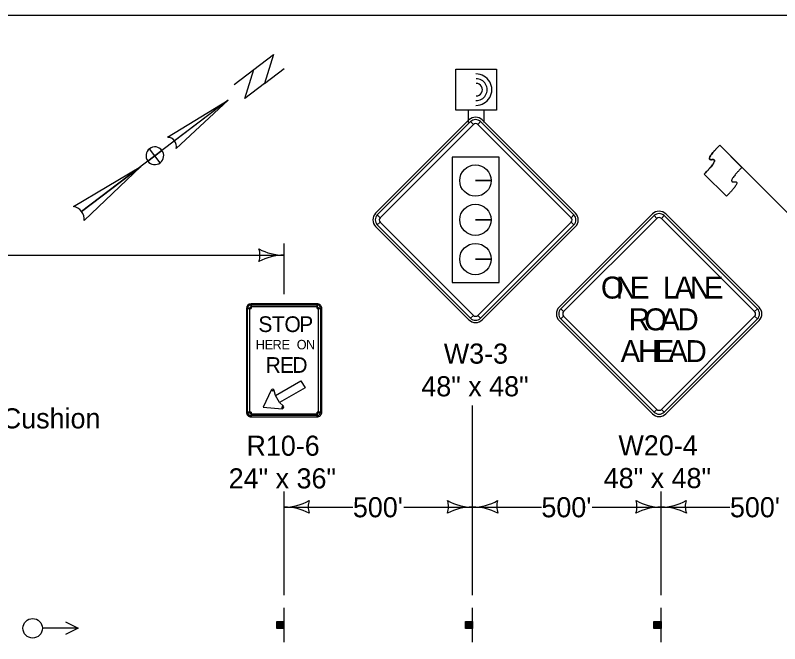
# Model space of a CAD drawing. Extents: x -2134934 to -2119606, y -2139046 to -2137036.
# Drawn here: x -2132728 to -2132120, y -2137536 to -2137036 of the extents above; entities that cross this region are included whole.
import ezdxf

# ---------------------------------------------------------------- set-up
doc = ezdxf.new("R2010")
doc.units = 0
for name, color, linetype in [('Default', 7, 'Continuous'), ('dsnCellElements', 7, 'Continuous'), ('dsnCellsScaleBlock', 7, 'Continuous'), ('dsnStdLabel', 7, 'Continuous'), ('Level 2', 7, 'Continuous'), ('Level 5', 7, 'Continuous')]:
    doc.layers.add(name, color=color, linetype=linetype)

msp = doc.modelspace()

# ---------------------------------------------------------------- linework, layer by layer
at = {"layer": 'Default'}
msp.add_lwpolyline([(-2134934.44, -2137035.95), (-2131799.45, -2137035.95), (-2131799.45, -2139045.94), (-2134934.44, -2139045.94)], close=True, dxfattribs=at)
at = {"layer": 'dsnCellElements'}
for centre, radius, start, end in [((-2132550.08, -2137226.98), 16.42, 342.26665, 17.73335), ((-2132514.45, -2137184.48), 42.5, 241.92751, 270), ((-2132514.45, -2137269.48), 42.5, 90, 118.07249)]:
    msp.add_arc(centre, radius, start, end, dxfattribs=at)
at = {"layer": 'dsnCellsScaleBlock'}
for p, q in [((-2132558.93, -2137103.5), (-2132675.59, -2137192.09)), ((-2132558.93, -2137103.5), (-2132600.39, -2137142.06)), ((-2132607.2, -2137133.09), (-2132607.2, -2137133.09)), ((-2132606.66, -2137132.95), (-2132605.09, -2137133.07)), ((-2132622.86, -2137152.05), (-2132622.87, -2137152.06)), ((-2132682.09, -2137188.19), (-2132628.47, -2137156.31))]:
    msp.add_line(p, q, dxfattribs=at)
for points in [[(-2132554.21, -2137091.08), (-2132522.8, -2137067.23), (-2132529.99, -2137090.37), (-2132514.28, -2137078.45)], [(-2132607.2, -2137133.09), (-2132558.93, -2137103.5), (-2132601.55, -2137135.87)], [(-2132622.87, -2137152.06), (-2132617.26, -2137147.8), (-2132621.52, -2137142.19)], [(-2132613, -2137153.41), (-2132617.26, -2137147.8), (-2132611.65, -2137143.54)], [(-2132675.59, -2137192.09), (-2132628.47, -2137156.31), (-2132673.57, -2137199.41)]]:
    msp.add_lwpolyline(points, dxfattribs=at)
msp.add_lwpolyline([(-2132545.69, -2137102.3), (-2132538.5, -2137079.15), (-2132522.8, -2137067.23), (-2132529.99, -2137090.37)], close=True, dxfattribs=at)
for centre, radius, start, end in [((-2132607.16, -2137140.13), 7.04, 37.23253, 90.33788), ((-2132607.15, -2137140.13), 7.04, 344.06021, 37.23398), ((-2132617.26, -2137147.8), 7.04, 127.21215, 217.21215), ((-2132617.26, -2137147.8), 7.04, 37.21215, 127.21215), ((-2132617.26, -2137147.8), 7.04, 307.21215, 37.21215), ((-2132617.26, -2137147.8), 7.04, 217.21215, 307.21215), ((-2132683.72, -2137198.26), 10.2, 37.20154, 80.8311), ((-2132683.72, -2137198.27), 10.21, 353.61421, 37.21279)]:
    msp.add_arc(centre, radius, start, end, dxfattribs=at)
at = {"layer": 'dsnStdLabel'}
for p, q in [((-2132367.37, -2137119.33), (-2132441.62, -2137193.57)), ((-2132366.05, -2137120.65), (-2132363.84, -2137122.86)), ((-2132360.3, -2137122.86), (-2132358.09, -2137120.65)), ((-2132282.52, -2137193.57), (-2132356.77, -2137119.33)), ((-2132110.46, -2137196.68), (-2132167.8, -2137139.38)), ((-2132167.8, -2137139.38), (-2132150.11, -2137157.06)), ((-2132162.49, -2137180.05), (-2132180.17, -2137162.37)), ((-2132349.66, -2137167.55), (-2132362.16, -2137167.55)), ((-2132362.16, -2137167.55), (-2132349.66, -2137167.55)), ((-2132438.08, -2137197.11), (-2132440.29, -2137194.9)), ((-2132221.34, -2137194.14), (-2132295.58, -2137268.39)), ((-2132283.85, -2137194.9), (-2132286.06, -2137197.11)), ((-2132136.48, -2137268.39), (-2132210.73, -2137194.14)), ((-2132440.29, -2137202.85), (-2132438.08, -2137200.64)), ((-2132349.66, -2137198.8), (-2132362.16, -2137198.8)), ((-2132362.16, -2137198.8), (-2132349.66, -2137198.8)), ((-2132286.06, -2137200.64), (-2132283.85, -2137202.85)), ((-2132220.01, -2137195.47), (-2132217.8, -2137197.68)), ((-2132214.27, -2137197.68), (-2132212.06, -2137195.47)), ((-2132441.62, -2137204.18), (-2132367.37, -2137278.43)), ((-2132356.77, -2137278.43), (-2132282.52, -2137204.18)), ((-2132349.66, -2137230.05), (-2132362.16, -2137230.05)), ((-2132362.16, -2137230.05), (-2132349.66, -2137230.05)), ((-2132540.7, -2137269.41), (-2132540.7, -2137265.66)), ((-2132540.7, -2137268.16), (-2132540.7, -2137266.6)), ((-2132488.2, -2137265.66), (-2132488.2, -2137269.41)), ((-2132488.2, -2137266.6), (-2132488.2, -2137268.16)), ((-2132544.45, -2137269.41), (-2132540.7, -2137269.41)), ((-2132543.51, -2137269.41), (-2132541.95, -2137269.41)), ((-2132488.2, -2137269.41), (-2132484.45, -2137269.41)), ((-2132486.95, -2137269.41), (-2132485.38, -2137269.41)), ((-2132292.05, -2137271.93), (-2132294.26, -2137269.72)), ((-2132137.81, -2137269.72), (-2132140.02, -2137271.93)), ((-2132363.84, -2137274.89), (-2132366.05, -2137277.1)), ((-2132358.09, -2137277.1), (-2132360.3, -2137274.89)), ((-2132295.58, -2137279), (-2132221.34, -2137353.24)), ((-2132294.26, -2137277.67), (-2132292.05, -2137275.46)), ((-2132210.73, -2137353.24), (-2132136.48, -2137279)), ((-2132140.02, -2137275.46), (-2132137.81, -2137277.67)), ((-2132524.59, -2137334.4), (-2132523.48, -2137334.98)), ((-2132523.48, -2137334.98), (-2132522.26, -2137334.7)), ((-2132540.7, -2137351.91), (-2132544.45, -2137351.91)), ((-2132541.95, -2137351.91), (-2132543.51, -2137351.91)), ((-2132540.7, -2137355.66), (-2132540.7, -2137351.91)), ((-2132515.98, -2137347.97), (-2132516.03, -2137349.22)), ((-2132515.13, -2137347.05), (-2132515.98, -2137347.97)), ((-2132484.45, -2137351.91), (-2132488.2, -2137351.91)), ((-2132488.2, -2137351.91), (-2132488.2, -2137355.66)), ((-2132485.38, -2137351.91), (-2132486.95, -2137351.91)), ((-2132217.8, -2137349.71), (-2132220.01, -2137351.92)), ((-2132212.06, -2137351.92), (-2132214.27, -2137349.71)), ((-2132540.7, -2137354.72), (-2132540.7, -2137353.16)), ((-2132488.2, -2137353.16), (-2132488.2, -2137354.72))]:
    msp.add_line(p, q, dxfattribs=at)
for points in [[(-2132366.05, -2137120.65), (-2132440.29, -2137194.9), (-2132438.08, -2137197.11), (-2132363.84, -2137122.86), (-2132366.05, -2137120.65)], [(-2132283.85, -2137194.9), (-2132358.09, -2137120.65), (-2132360.3, -2137122.86), (-2132286.06, -2137197.11), (-2132283.85, -2137194.9)], [(-2132343.34, -2137148.93), (-2132380.8, -2137148.93), (-2132380.8, -2137248.82), (-2132343.34, -2137248.82), (-2132343.34, -2137148.93)], [(-2132440.29, -2137202.85), (-2132366.05, -2137277.1), (-2132363.84, -2137274.89), (-2132438.08, -2137200.64), (-2132440.29, -2137202.85)], [(-2132358.09, -2137277.1), (-2132283.85, -2137202.85), (-2132286.06, -2137200.64), (-2132360.3, -2137274.89), (-2132358.09, -2137277.1)], [(-2132220.01, -2137195.47), (-2132294.26, -2137269.72), (-2132292.05, -2137271.93), (-2132217.8, -2137197.68), (-2132220.01, -2137195.47)], [(-2132137.81, -2137269.72), (-2132212.06, -2137195.47), (-2132214.27, -2137197.68), (-2132140.02, -2137271.93), (-2132137.81, -2137269.72)], [(-2132540.7, -2137355.66), (-2132488.2, -2137355.66), (-2132488.2, -2137351.91), (-2132484.45, -2137351.91), (-2132484.45, -2137269.41), (-2132488.2, -2137269.41), (-2132488.2, -2137265.66), (-2132540.7, -2137265.66), (-2132540.7, -2137269.41), (-2132544.45, -2137269.41), (-2132544.45, -2137351.91), (-2132540.7, -2137351.91), (-2132540.7, -2137355.66)], [(-2132488.2, -2137268.16), (-2132540.7, -2137268.16), (-2132540.7, -2137266.6), (-2132488.2, -2137266.6), (-2132488.2, -2137268.16)], [(-2132541.95, -2137269.41), (-2132541.95, -2137351.91), (-2132543.51, -2137351.91), (-2132543.51, -2137269.41), (-2132541.95, -2137269.41)], [(-2132486.95, -2137351.91), (-2132486.95, -2137269.41), (-2132485.38, -2137269.41), (-2132485.38, -2137351.91), (-2132486.95, -2137351.91)], [(-2132294.26, -2137277.67), (-2132220.01, -2137351.92), (-2132217.8, -2137349.71), (-2132292.05, -2137275.46), (-2132294.26, -2137277.67)], [(-2132212.06, -2137351.92), (-2132137.81, -2137277.67), (-2132140.02, -2137275.46), (-2132214.27, -2137349.71), (-2132212.06, -2137351.92)], [(-2132501.07, -2137326.91), (-2132497.79, -2137332.6), (-2132518.1, -2137344.32), (-2132521.38, -2137338.64), (-2132501.07, -2137326.91)], [(-2132531.1, -2137348.04), (-2132516.03, -2137349.22), (-2132515.98, -2137347.97), (-2132515.13, -2137347.05), (-2132518.1, -2137344.32), (-2132521.38, -2137338.64), (-2132522.26, -2137334.7), (-2132523.48, -2137334.98), (-2132524.59, -2137334.4), (-2132531.1, -2137348.04)], [(-2132540.7, -2137353.16), (-2132488.2, -2137353.16), (-2132488.2, -2137354.72), (-2132540.7, -2137354.72), (-2132540.7, -2137353.16)]]:
    msp.add_lwpolyline(points, close=True, dxfattribs=at)
for centre in [(-2132362.16, -2137167.55), (-2132362.16, -2137198.8), (-2132362.16, -2137230.05)]:
    msp.add_circle(centre, 12.5, dxfattribs=at)
for centre, radius, start, end in [((-2132362.07, -2137124.63), 7.5, 44.99999, 134.99974), ((-2132362.07, -2137124.63), 5.62, 44.99999, 134.99974), ((-2132362.07, -2137124.63), 2.5, 44.99999, 134.99974), ((-2132436.32, -2137198.88), 7.5, 134.99974, 224.99995), ((-2132436.32, -2137198.88), 5.62, 134.99974, 224.99995), ((-2132287.83, -2137198.88), 5.62, 315.00016, 44.9998), ((-2132287.83, -2137198.88), 7.5, 315.00016, 44.9998), ((-2132216.03, -2137199.45), 7.5, 44.99999, 134.99974), ((-2132216.03, -2137199.45), 5.62, 44.99999, 134.99974), ((-2132436.32, -2137198.88), 2.5, 134.99974, 224.99995), ((-2132287.83, -2137198.88), 2.5, 315.00016, 44.9998), ((-2132216.03, -2137199.45), 2.5, 44.99999, 134.99974), ((-2132540.7, -2137269.41), 3.75, 90.00021, 179.99985), ((-2132540.7, -2137269.41), 2.81, 90.00021, 179.99985), ((-2132488.2, -2137269.41), 3.75, 0, 90.00021), ((-2132488.2, -2137269.41), 2.81, 0, 90.00021), ((-2132540.7, -2137269.41), 1.25, 90.00021, 179.99985), ((-2132488.2, -2137269.41), 1.25, 0, 90.00021), ((-2132290.28, -2137273.69), 7.5, 134.99974, 224.99995), ((-2132290.28, -2137273.69), 5.62, 134.99974, 224.99995), ((-2132290.28, -2137273.69), 2.5, 134.99974, 224.99995), ((-2132141.79, -2137273.69), 2.5, 315.00016, 44.9998), ((-2132141.79, -2137273.69), 5.62, 315.00016, 44.9998), ((-2132141.79, -2137273.69), 7.5, 315.00016, 44.9998), ((-2132362.07, -2137273.12), 7.5, 224.99995, 315.00016), ((-2132362.07, -2137273.12), 5.62, 224.99995, 315.00016), ((-2132362.07, -2137273.12), 2.5, 224.99995, 315.00016), ((-2132523.48, -2137334.98), 1.25, 12.62232, 152.27557), ((-2132540.7, -2137351.91), 3.75, 179.99985, 270.00006), ((-2132540.7, -2137351.91), 2.81, 179.99985, 270.00006), ((-2132540.7, -2137351.91), 1.25, 179.99985, 270.00006), ((-2132515.98, -2137347.97), 1.25, 267.72427, 47.37758), ((-2132488.2, -2137351.91), 3.75, 270.00006, 0.00027), ((-2132488.2, -2137351.91), 2.81, 270.00006, 0.00027), ((-2132488.2, -2137351.91), 1.25, 270.00006, 0.00027), ((-2132216.03, -2137347.94), 5.62, 224.99995, 315.00016), ((-2132216.03, -2137347.94), 2.5, 224.99995, 315.00016), ((-2132216.03, -2137347.94), 7.5, 224.99995, 315.00016)]:
    msp.add_arc(centre, radius, start, end, dxfattribs=at)
for points in [[(-2132180.17, -2137162.37), (-2132167.8, -2137149.99), (-2132180.17, -2137151.77), (-2132167.8, -2137139.38)], [(-2132150.11, -2137157.06), (-2132162.49, -2137169.44), (-2132150.12, -2137167.67), (-2132162.49, -2137180.05)]]:
    msp.add_open_spline(points, degree=2, dxfattribs=at)
at = {"layer": 'Level 2'}
for p, q in [((-2132367.91, -2137111.41), (-2132367.91, -2137121.41)), ((-2132355.41, -2137111.41), (-2132355.41, -2137121.41)), ((-2132514.45, -2137258.09), (-2132514.45, -2137217.69)), ((-2133178.02, -2137226.98), (-2132514.45, -2137226.98)), ((-2132364.45, -2137497.66), (-2132364.45, -2137346.75)), ((-2132514.45, -2137497.66), (-2132514.45, -2137415.16)), ((-2132214.45, -2137497.66), (-2132214.45, -2137415.16)), ((-2132514.45, -2137427.66), (-2132459.7, -2137427.66)), ((-2132419.2, -2137427.66), (-2132364.45, -2137427.66)), ((-2132364.45, -2137427.66), (-2132309.7, -2137427.66)), ((-2132269.2, -2137427.66), (-2132214.45, -2137427.66)), ((-2132214.45, -2137427.66), (-2132159.7, -2137427.66)), ((-2132514.45, -2137535.16), (-2132514.45, -2137507.66)), ((-2132364.45, -2137535.16), (-2132364.45, -2137507.66)), ((-2132214.45, -2137535.16), (-2132214.45, -2137507.66)), ((-2132519.77, -2137524.3), (-2132519.77, -2137518.71)), ((-2132519.45, -2137518.71), (-2132519.45, -2137524.3)), ((-2132519.23, -2137524.3), (-2132519.23, -2137518.71)), ((-2132518.91, -2137518.71), (-2132518.91, -2137524.3)), ((-2132518.68, -2137524.3), (-2132518.7, -2137518.71)), ((-2132518.27, -2137518.71), (-2132518.25, -2137524.3)), ((-2132518.05, -2137524.3), (-2132518.05, -2137518.71)), ((-2132517.62, -2137518.71), (-2132517.62, -2137524.3)), ((-2132517.24, -2137524.3), (-2132517.24, -2137518.71)), ((-2132516.92, -2137518.71), (-2132516.9, -2137524.3)), ((-2132516.7, -2137524.3), (-2132516.7, -2137518.71)), ((-2132516.43, -2137518.71), (-2132516.43, -2137524.3)), ((-2132516.1, -2137524.3), (-2132516.1, -2137518.71)), ((-2132515.89, -2137518.71), (-2132515.89, -2137524.3)), ((-2132515.67, -2137524.3), (-2132515.67, -2137518.71)), ((-2132515.4, -2137518.71), (-2132515.4, -2137524.3)), ((-2132515.14, -2137524.3), (-2132515.14, -2137518.71)), ((-2132514.86, -2137518.71), (-2132514.86, -2137524.3)), ((-2132369.77, -2137524.3), (-2132369.77, -2137518.71)), ((-2132369.45, -2137518.71), (-2132369.45, -2137524.3)), ((-2132369.23, -2137524.3), (-2132369.23, -2137518.71)), ((-2132368.91, -2137518.71), (-2132368.91, -2137524.3)), ((-2132368.68, -2137524.3), (-2132368.7, -2137518.71)), ((-2132368.27, -2137518.71), (-2132368.25, -2137524.3)), ((-2132368.05, -2137524.3), (-2132368.05, -2137518.71)), ((-2132367.62, -2137518.71), (-2132367.62, -2137524.3)), ((-2132367.24, -2137524.3), (-2132367.24, -2137518.71)), ((-2132366.92, -2137518.71), (-2132366.9, -2137524.3)), ((-2132366.7, -2137524.3), (-2132366.7, -2137518.71)), ((-2132366.43, -2137518.71), (-2132366.43, -2137524.3)), ((-2132366.1, -2137524.3), (-2132366.1, -2137518.71)), ((-2132365.89, -2137518.71), (-2132365.89, -2137524.3)), ((-2132365.67, -2137524.3), (-2132365.67, -2137518.71)), ((-2132365.4, -2137518.71), (-2132365.4, -2137524.3)), ((-2132365.14, -2137524.3), (-2132365.14, -2137518.71)), ((-2132364.86, -2137518.71), (-2132364.86, -2137524.3)), ((-2132219.77, -2137524.3), (-2132219.77, -2137518.71)), ((-2132219.45, -2137518.71), (-2132219.45, -2137524.3)), ((-2132219.23, -2137524.3), (-2132219.23, -2137518.71)), ((-2132218.91, -2137518.71), (-2132218.91, -2137524.3)), ((-2132218.69, -2137524.3), (-2132218.7, -2137518.71)), ((-2132218.27, -2137518.71), (-2132218.25, -2137524.3)), ((-2132218.05, -2137524.3), (-2132218.05, -2137518.71)), ((-2132217.62, -2137518.71), (-2132217.62, -2137524.3)), ((-2132217.24, -2137524.3), (-2132217.24, -2137518.71)), ((-2132216.92, -2137518.71), (-2132216.9, -2137524.3)), ((-2132216.7, -2137524.3), (-2132216.7, -2137518.71)), ((-2132216.43, -2137518.71), (-2132216.43, -2137524.3)), ((-2132216.1, -2137524.3), (-2132216.1, -2137518.71)), ((-2132215.89, -2137518.71), (-2132215.89, -2137524.3)), ((-2132215.67, -2137524.3), (-2132215.67, -2137518.71)), ((-2132215.4, -2137518.71), (-2132215.4, -2137524.3)), ((-2132215.14, -2137524.3), (-2132215.14, -2137518.71)), ((-2132214.86, -2137518.71), (-2132214.86, -2137524.3)), ((-2132706.71, -2137523.68), (-2132678.77, -2137523.68))]:
    msp.add_line(p, q, dxfattribs=at)
for points in [[(-2132377.91, -2137111.41), (-2132377.91, -2137078.91), (-2132345.41, -2137078.91), (-2132345.41, -2137111.41)], [(-2132514.54, -2137518.71), (-2132514.54, -2137524.34), (-2132520.17, -2137524.34), (-2132520.17, -2137518.71)], [(-2132364.54, -2137518.71), (-2132364.54, -2137524.34), (-2132370.17, -2137524.34), (-2132370.17, -2137518.71)], [(-2132214.54, -2137518.71), (-2132214.54, -2137524.34), (-2132220.17, -2137524.34), (-2132220.17, -2137518.71)]]:
    msp.add_lwpolyline(points, close=True, dxfattribs=at)
msp.add_lwpolyline([(-2132688.4, -2137518.86), (-2132678.4, -2137523.86), (-2132688.4, -2137528.86)], dxfattribs=at)
msp.add_circle((-2132714.45, -2137524.04), 7.74, dxfattribs=at)
for centre, radius, start, end in [((-2132361.65, -2137095.18), 12.5, 269.40414, 90.54446), ((-2132361.65, -2137095.18), 12.5, 269.40414, 90.54446), ((-2132361.65, -2137095.18), 8.75, 269.40414, 90.54446), ((-2132361.65, -2137095.18), 5, 269.40414, 90.54446), ((-2132515.2, -2137385.17), 42.5, 271.0176, 299.07249), ((-2132478.83, -2137427.04), 16.42, 163.26665, 198.73335), ((-2132400.06, -2137427.04), 16.42, 341.26665, 16.73335), ((-2132363.69, -2137385.17), 42.5, 240.92751, 268.9824), ((-2132365.2, -2137385.17), 42.5, 271.0176, 299.07249), ((-2132328.83, -2137427.04), 16.42, 163.26665, 198.73335), ((-2132250.06, -2137427.04), 16.42, 341.26665, 16.73335), ((-2132213.69, -2137385.17), 42.5, 240.92751, 268.9824), ((-2132215.2, -2137385.17), 42.5, 271.0176, 299.07249), ((-2132178.83, -2137427.04), 16.42, 163.26665, 198.73335), ((-2132513.72, -2137470.15), 42.5, 62.92751, 90.9824), ((-2132365.17, -2137470.15), 42.5, 89.0176, 117.07249), ((-2132363.72, -2137470.15), 42.5, 62.92751, 90.9824), ((-2132215.17, -2137470.15), 42.5, 89.0176, 117.07249), ((-2132213.72, -2137470.15), 42.5, 62.92751, 90.9824)]:
    msp.add_arc(centre, radius, start, end, dxfattribs=at)
at = {"layer": 'Level 5'}
msp.add_line((-2132180.17, -2137162.37), (-2132162.49, -2137180.05), dxfattribs=at)
for points in [[(-2132167.8, -2137139.38), (-2132180.17, -2137151.77), (-2132167.8, -2137149.99), (-2132180.17, -2137162.37)], [(-2132150.11, -2137157.06), (-2132162.49, -2137169.44), (-2132150.12, -2137167.67), (-2132162.49, -2137180.05)]]:
    msp.add_open_spline(points, degree=2, dxfattribs=at)

# ---------------------------------------------------------------- texts
at = {"layer": 'dsnStdLabel'}
for s, height, p in [('O', 17.5, (-2132262.32, -2137261.51)), ('N', 17.5, (-2132250.54, -2137261.51)), ('E', 17.5, (-2132239.32, -2137261.51)), ('L', 17.5, (-2132213.07, -2137261.51)), ('A', 17.5, (-2132203.87, -2137261.51)), ('N', 17.5, (-2132191.6, -2137261.51)), ('E', 17.5, (-2132180.37, -2137261.51)), ('R', 17.5, (-2132240.21, -2137286.82)), ('O', 17.5, (-2132227.92, -2137286.82)), ('A', 17.5, (-2132215.08, -2137286.82)), ('D', 17.5, (-2132201.43, -2137286.82)), ('S', 12.5, (-2132534.89, -2137288.16)), ('T', 12.5, (-2132524.13, -2137288.16)), ('O', 12.5, (-2132514.14, -2137288.16)), ('P', 12.5, (-2132502.4, -2137288.16)), ('H', 7.5, (-2132536.97, -2137301.91)), ('E', 7.5, (-2132529.82, -2137301.91)), ('R', 7.5, (-2132523.56, -2137301.91)), ('E', 7.5, (-2132516.41, -2137301.91)), ('O', 7.5, (-2132504.34, -2137301.91)), ('N', 7.5, (-2132496.96, -2137301.91)), ('W3-3', 16, (-2132387.36, -2137313.34)), ('A', 17.5, (-2132246.65, -2137312.13)), ('H', 17.5, (-2132232.78, -2137312.13)), ('E', 17.5, (-2132219.57, -2137312.13)), ('A', 17.5, (-2132208.85, -2137312.13)), ('D', 17.5, (-2132194.99, -2137312.13)), ('R', 12.5, (-2132529.13, -2137320.66)), ('E', 12.5, (-2132517.8, -2137320.66)), ('D', 12.5, (-2132507.84, -2137320.66)), ('48" x 48"', 16, (-2132405.24, -2137339.34)), ('R10-6', 16, (-2132544.37, -2137386.66)), ('W20-4', 16, (-2132248.4, -2137386.44)), ('24" x 36"', 16, (-2132558.51, -2137412.66)), ('48" x 48"', 16, (-2132260.1, -2137412.44))]:
    msp.add_text(s, height=height, dxfattribs=at).set_placement(p)
at = {"layer": 'Level 2'}
for s, p in [('Temporary Crash Cushion', (-2132911.44, -2137364.9)), ("500'", (-2132459.7, -2137435.66)), ("500'", (-2132309.7, -2137435.66)), ("500'", (-2132159.7, -2137435.66))]:
    msp.add_text(s, height=16, dxfattribs=at).set_placement(p)

doc.saveas('drawing.dxf')
